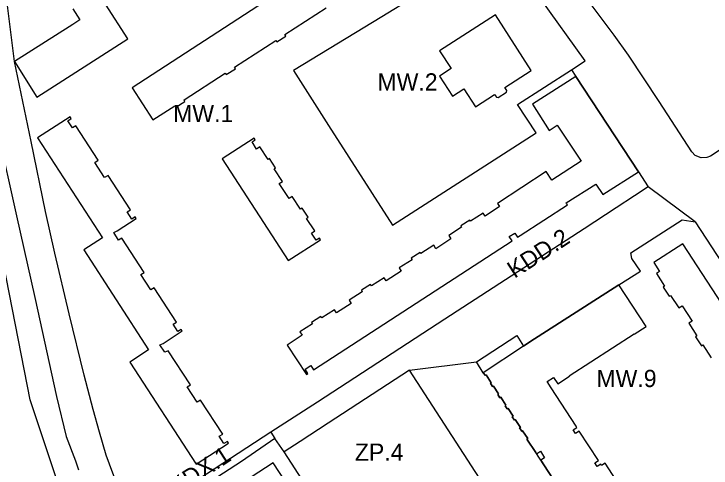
# Model space of a CAD drawing. Extents: x 7424052 to 7425705, y 5546602 to 5547569.
# Drawn here: x 7424769.6 to 7424972, y 5547200.9 to 5547332.7 of the extents above; entities that cross this region are included whole.
import ezdxf

# ---------------------------------------------------------------- set-up
doc = ezdxf.new("R2010")
doc.units = 0
for name, color, linetype in [('linie rozgraniczające', 7, 'Continuous'), ('nieprzekraczalne linie zabudowy', 7, 'Continuous'), ('obowiazujace linie zabudowy', 7, 'Continuous'), ('przeznaczenia terenów', 7, 'Continuous')]:
    doc.layers.add(name, color=color, linetype=linetype)

msp = doc.modelspace()

# ---------------------------------------------------------------- linework, layer by layer
at = {"layer": 'linie rozgraniczające'}
for p, q in [((7424910.29, 5547352.59), (7424876.38, 5547331.94)), ((7424943.81, 5547326.62), (7424931.1, 5547343.77)), ((7424769.83, 5547318.95), (7424767.07, 5547340.61)), ((7424935.47, 5547319.1), (7424922.33, 5547337.45)), ((7424876.38, 5547331.94), (7424850.76, 5547316.34)), ((7424948.03, 5547320.79), (7424943.81, 5547326.62)), ((7424956.87, 5547307.29), (7424948.03, 5547320.79)), ((7424774.64, 5547295.74), (7424769.83, 5547318.95)), ((7424931.41, 5547316.49), (7424935.47, 5547319.1)), ((7424850.76, 5547316.34), (7424860.98, 5547300.34)), ((7424915.81, 5547306.47), (7424931.41, 5547316.49)), ((7424931.41, 5547316.49), (7424932.69, 5547314.55)), ((7424932.69, 5547314.55), (7424950.88, 5547286.89)), ((7424966.38, 5547292.73), (7424956.87, 5547307.29)), ((7424921.18, 5547298.19), (7424915.81, 5547306.47)), ((7424764.44, 5547300.62), (7424770.4, 5547274.14)), ((7424988.18, 5547302.22), (7424971.75, 5547291.5)), ((7424860.98, 5547300.34), (7424879.48, 5547271.4)), ((7424879.48, 5547271.4), (7424921.18, 5547298.19)), ((7424778.79, 5547275.39), (7424774.64, 5547295.74)), ((7424967.37, 5547291.63), (7424966.38, 5547292.73)), ((7424969.1, 5547290.96), (7424967.37, 5547291.63)), ((7424970.72, 5547291.07), (7424969.1, 5547290.96)), ((7424971.75, 5547291.5), (7424970.72, 5547291.07)), ((7424950.88, 5547286.89), (7424953.73, 5547282.55)), ((7424953.73, 5547282.55), (7424949.7, 5547279.92)), ((7424967.35, 5547272.4), (7424953.73, 5547282.55)), ((7424949.7, 5547279.92), (7424944.41, 5547276.45)), ((7424944.41, 5547276.45), (7424935.15, 5547270.42)), ((7424770.4, 5547274.14), (7424775.71, 5547250.48)), ((7424781.47, 5547263.28), (7424778.79, 5547275.39)), ((7424948.65, 5547263.37), (7424963.59, 5547272.95)), ((7424963.59, 5547272.95), (7424967.35, 5547272.4)), ((7424967.35, 5547272.4), (7425007.07, 5547211.22)), ((7424935.15, 5547270.42), (7424894.68, 5547244.14)), ((7424785.68, 5547245.66), (7424781.47, 5547263.28)), ((7424948.95, 5547261.77), (7424948.65, 5547263.37)), ((7424951.45, 5547258.07), (7424948.95, 5547261.77)), ((7424945.18, 5547254.14), (7424951.45, 5547258.07)), ((7424919.41, 5547237.58), (7424945.18, 5547254.14)), ((7424775.71, 5547250.48), (7424781.99, 5547221.75)), ((7424789.98, 5547227.95), (7424785.68, 5547245.66)), ((7424894.68, 5547244.14), (7424857.73, 5547220.11)), ((7424903.86, 5547231.82), (7424915.61, 5547239.38)), ((7424915.61, 5547239.38), (7424917.57, 5547236.35)), ((7424917.57, 5547236.35), (7424919.41, 5547237.58)), ((7424884.42, 5547229.37), (7424903.86, 5547231.82)), ((7424905.84, 5547228.59), (7424903.86, 5547231.82)), ((7424792.66, 5547217.92), (7424789.98, 5547227.95)), ((7424884.42, 5547229.37), (7424860.86, 5547213.93)), ((7424905.84, 5547196.33), (7424884.42, 5547229.37)), ((7424906.46, 5547227.84), (7424905.84, 5547228.59)), ((7424906.71, 5547228), (7424906.46, 5547227.84)), ((7424908.17, 5547225.7), (7424906.71, 5547228)), ((7424907.91, 5547225.56), (7424908.17, 5547225.7)), ((7424908.56, 5547224.59), (7424907.91, 5547225.56)), ((7424908.81, 5547224.75), (7424908.56, 5547224.59)), ((7424910.29, 5547222.46), (7424908.81, 5547224.75)), ((7424781.99, 5547221.75), (7424784.83, 5547210.14)), ((7424910.05, 5547222.29), (7424910.29, 5547222.46)), ((7424910.67, 5547221.34), (7424910.05, 5547222.29)), ((7424857.73, 5547220.11), (7424844.22, 5547211.34)), ((7424910.93, 5547221.5), (7424910.67, 5547221.34)), ((7424912.41, 5547219.21), (7424910.93, 5547221.5)), ((7424794.43, 5547211.37), (7424792.66, 5547217.92)), ((7424912.17, 5547219.05), (7424912.41, 5547219.21)), ((7424912.79, 5547218.12), (7424912.17, 5547219.05)), ((7424913.04, 5547218.27), (7424912.79, 5547218.12)), ((7424914.52, 5547215.98), (7424913.04, 5547218.27)), ((7424914.28, 5547215.83), (7424914.52, 5547215.98)), ((7424914.91, 5547214.88), (7424914.28, 5547215.83)), ((7424860.86, 5547213.93), (7424852.68, 5547208.65)), ((7424915.15, 5547215.04), (7424914.91, 5547214.88)), ((7424916.64, 5547212.74), (7424915.15, 5547215.04)), ((7424916.39, 5547212.57), (7424916.64, 5547212.74)), ((7424917.03, 5547211.63), (7424916.39, 5547212.57)), ((7424917.23, 5547211.76), (7424917.03, 5547211.63)), ((7424918.74, 5547209.48), (7424917.23, 5547211.76)), ((7424784.83, 5547210.14), (7424787.48, 5547203.06)), ((7424796.45, 5547204.69), (7424794.43, 5547211.37)), ((7424844.22, 5547211.34), (7424803.72, 5547185.05)), ((7424845.37, 5547209.56), (7424835.69, 5547202.88)), ((7424844.22, 5547211.34), (7424845.37, 5547209.56)), ((7424848.08, 5547205.67), (7424845.37, 5547209.56)), ((7424918.51, 5547209.35), (7424918.74, 5547209.48)), ((7424852.68, 5547208.65), (7424848.08, 5547205.67)), ((7424921.08, 5547205.48), (7424918.51, 5547209.35)), ((7424869.3, 5547172.76), (7424848.08, 5547205.67)), ((7424928.48, 5547194.19), (7424921.08, 5547205.48)), ((7424803.72, 5547185.05), (7424796.45, 5547204.69)), ((7424787.48, 5547203.06), (7424788.42, 5547200.44)), ((7424835.69, 5547202.88), (7424804.56, 5547182.77))]:
    msp.add_line(p, q, dxfattribs=at)
at = {"layer": 'nieprzekraczalne linie zabudowy'}
for p, q in [((7424774.34, 5547220.72), (7424753.24, 5547328.2)), ((7424783.94, 5547191.96), (7424774.34, 5547220.72))]:
    msp.add_line(p, q, dxfattribs=at)
at = {"layer": 'obowiazujace linie zabudowy'}
for p, q in [((7424863.83, 5547350.2), (7424803.91, 5547311.34)), ((7424802.68, 5547325.47), (7424796.23, 5547335.59)), ((7424786.74, 5547334.23), (7424788.81, 5547331)), ((7424848.3, 5547326.8), (7424860.23, 5547334.52)), ((7424788.81, 5547331), (7424786.73, 5547329.68)), ((7424786.73, 5547329.68), (7424769.83, 5547318.95)), ((7424848.57, 5547326.33), (7424848.3, 5547326.8)), ((7424776.3, 5547308.56), (7424802.68, 5547325.47)), ((7424833.61, 5547317.29), (7424845.61, 5547325.06)), ((7424845.61, 5547325.06), (7424845.91, 5547324.6)), ((7424845.91, 5547324.6), (7424848.57, 5547326.33)), ((7424769.83, 5547318.95), (7424776.3, 5547308.56)), ((7424831.28, 5547315.13), (7424833.92, 5547316.81)), ((7424833.92, 5547316.81), (7424833.61, 5547317.29)), ((7424819, 5547307.82), (7424830.97, 5547315.57)), ((7424830.97, 5547315.57), (7424831.28, 5547315.13)), ((7424932.69, 5547314.55), (7424920.11, 5547306.55)), ((7424950.88, 5547286.89), (7424932.69, 5547314.55)), ((7424803.91, 5547311.34), (7424809.97, 5547301.97)), ((7424816.64, 5547305.64), (7424819.27, 5547307.36)), ((7424819.27, 5547307.36), (7424819, 5547307.82)), ((7424920.11, 5547306.55), (7424924.99, 5547298.94)), ((7424809.97, 5547301.97), (7424816.35, 5547306.1)), ((7424816.35, 5547306.1), (7424816.64, 5547305.64)), ((7424785.92, 5547302.86), (7424776.5, 5547296.79)), ((7424786.24, 5547302.37), (7424785.92, 5547302.86)), ((7424785.3, 5547301.75), (7424786.24, 5547302.37)), ((7424786.64, 5547299.64), (7424785.3, 5547301.75)), ((7424924.99, 5547298.94), (7424927.34, 5547300.5)), ((7424927.34, 5547300.5), (7424934.23, 5547290.01)), ((7424787.62, 5547300.24), (7424786.64, 5547299.64)), ((7424794.1, 5547290.28), (7424787.62, 5547300.24)), ((7424776.5, 5547296.79), (7424795.33, 5547267.77)), ((7424793.14, 5547289.67), (7424794.1, 5547290.28)), ((7424795.97, 5547285.23), (7424793.14, 5547289.67)), ((7424934.23, 5547290.01), (7424925.72, 5547284.46)), ((7424924.1, 5547286.97), (7424909.99, 5547277.75)), ((7424925.72, 5547284.46), (7424924.1, 5547286.97)), ((7424940.56, 5547280.32), (7424950.88, 5547286.89)), ((7424796.96, 5547285.87), (7424795.97, 5547285.23)), ((7424803.44, 5547275.92), (7424796.96, 5547285.87)), ((7424929.95, 5547277.89), (7424938.53, 5547283.36)), ((7424938.53, 5547283.36), (7424940.56, 5547280.32)), ((7424910.59, 5547276.85), (7424906.41, 5547274.05)), ((7424909.99, 5547277.75), (7424910.59, 5547276.85)), ((7424916.54, 5547268.41), (7424930.33, 5547277.3)), ((7424930.03, 5547277.77), (7424929.95, 5547277.89)), ((7424930.33, 5547277.3), (7424930.03, 5547277.77)), ((7424802.47, 5547275.27), (7424803.44, 5547275.92)), ((7424803.81, 5547273.19), (7424802.47, 5547275.27)), ((7424905.84, 5547274.9), (7424902.16, 5547272.56)), ((7424906.41, 5547274.05), (7424905.84, 5547274.9)), ((7424799.56, 5547269.76), (7424805.11, 5547273.34)), ((7424804.8, 5547273.82), (7424803.81, 5547273.19)), ((7424805.11, 5547273.34), (7424804.8, 5547273.82)), ((7424901.91, 5547272.91), (7424899.3, 5547271.21)), ((7424902.16, 5547272.56), (7424901.91, 5547272.91)), ((7424899.51, 5547270.83), (7424895.83, 5547268.46)), ((7424899.3, 5547271.21), (7424899.51, 5547270.83)), ((7424798.6, 5547269.31), (7424799.56, 5547269.76)), ((7424799.99, 5547267.08), (7424798.6, 5547269.31)), ((7424895.83, 5547268.46), (7424896.48, 5547267.47)), ((7424913.4, 5547268.17), (7424915.04, 5547269.16)), ((7424914.22, 5547266.91), (7424913.4, 5547268.17)), ((7424915.04, 5547269.16), (7424915.83, 5547267.95)), ((7424915.83, 5547267.95), (7424916.54, 5547268.41)), ((7424795.33, 5547267.77), (7424789.88, 5547264.25)), ((7424800.92, 5547267.67), (7424799.99, 5547267.08)), ((7424807.44, 5547257.69), (7424800.92, 5547267.67)), ((7424856.62, 5547229.47), (7424914.22, 5547266.91)), ((7424896.48, 5547267.47), (7424892.12, 5547264.58)), ((7424789.88, 5547264.25), (7424808.73, 5547235.21)), ((7424891.46, 5547265.63), (7424887.76, 5547263.24)), ((7424892.12, 5547264.58), (7424891.46, 5547265.63)), ((7424887.55, 5547263.54), (7424884.93, 5547261.85)), ((7424887.76, 5547263.24), (7424887.55, 5547263.54)), ((7424885.17, 5547261.41), (7424881.47, 5547259.02)), ((7424884.93, 5547261.85), (7424885.17, 5547261.41)), ((7424882.06, 5547258.06), (7424877.66, 5547255.29)), ((7424881.47, 5547259.02), (7424882.06, 5547258.06)), ((7424806.51, 5547257.1), (7424807.44, 5547257.69)), ((7424809.36, 5547252.7), (7424806.51, 5547257.1)), ((7424877.1, 5547256.19), (7424873.45, 5547253.83)), ((7424877.66, 5547255.29), (7424877.1, 5547256.19)), ((7424873.17, 5547254.25), (7424870.49, 5547252.55)), ((7424873.45, 5547253.83), (7424873.17, 5547254.25)), ((7424945.18, 5547254.14), (7424919.41, 5547237.58)), ((7424953.09, 5547242.06), (7424945.18, 5547254.14)), ((7424810.3, 5547253.29), (7424809.36, 5547252.7)), ((7424816.82, 5547243.3), (7424810.3, 5547253.29)), ((7424870.71, 5547252.12), (7424866.92, 5547249.67)), ((7424870.49, 5547252.55), (7424870.71, 5547252.12)), ((7424867.48, 5547248.72), (7424863.21, 5547245.96)), ((7424866.92, 5547249.67), (7424867.48, 5547248.72)), ((7424862.63, 5547246.9), (7424859, 5547244.55)), ((7424863.21, 5547245.96), (7424862.63, 5547246.9)), ((7424858.71, 5547244.95), (7424856, 5547243.21)), ((7424859, 5547244.55), (7424858.71, 5547244.95)), ((7424815.87, 5547242.66), (7424816.82, 5547243.3)), ((7424817.21, 5547240.57), (7424815.87, 5547242.66)), ((7424856.33, 5547242.78), (7424852.62, 5547240.44)), ((7424856, 5547243.21), (7424856.33, 5547242.78)), ((7424949.69, 5547239.84), (7424953.09, 5547242.06)), ((7424812.98, 5547237.12), (7424818.49, 5547240.73)), ((7424818.19, 5547241.2), (7424817.21, 5547240.57)), ((7424818.49, 5547240.73), (7424818.19, 5547241.2)), ((7424852.62, 5547240.44), (7424853.31, 5547239.49)), ((7424930.78, 5547227.74), (7424949.61, 5547239.94)), ((7424949.61, 5547239.94), (7424949.69, 5547239.84)), ((7424853.31, 5547239.49), (7424848.96, 5547236.63)), ((7424812, 5547236.68), (7424812.98, 5547237.12)), ((7424813.39, 5547234.53), (7424812, 5547236.68)), ((7424848.96, 5547236.63), (7424854.54, 5547228.12)), ((7424917.57, 5547236.35), (7424905.84, 5547228.59)), ((7424919.41, 5547237.58), (7424917.57, 5547236.35)), ((7424808.73, 5547235.21), (7424803.29, 5547231.68)), ((7424814.36, 5547235.01), (7424813.39, 5547234.53)), ((7424820.87, 5547225.05), (7424814.36, 5547235.01)), ((7424803.29, 5547231.68), (7424822.49, 5547202.06)), ((7424854.17, 5547229.63), (7424855.8, 5547230.7)), ((7424854.97, 5547228.4), (7424854.17, 5547229.63)), ((7424855.8, 5547230.7), (7424856.62, 5547229.47)), ((7424854.54, 5547228.12), (7424854.97, 5547228.4)), ((7424905.84, 5547228.59), (7424906.46, 5547227.84)), ((7424906.46, 5547227.84), (7424906.71, 5547228)), ((7424906.71, 5547228), (7424908.17, 5547225.7)), ((7424927.47, 5547225.41), (7424930.86, 5547227.61)), ((7424930.86, 5547227.61), (7424930.78, 5547227.74)), ((7424908.17, 5547225.7), (7424907.91, 5547225.56)), ((7424924.35, 5547226.03), (7424926.24, 5547227.26)), ((7424925.55, 5547224.19), (7424924.35, 5547226.03)), ((7424926.24, 5547227.26), (7424927.47, 5547225.41)), ((7424819.95, 5547224.47), (7424820.87, 5547225.05)), ((7424822.85, 5547220.1), (7424819.95, 5547224.47)), ((7424907.91, 5547225.56), (7424908.56, 5547224.59)), ((7424908.56, 5547224.59), (7424908.81, 5547224.75)), ((7424908.81, 5547224.75), (7424910.29, 5547222.46)), ((7424932.8, 5547213.08), (7424925.55, 5547224.19)), ((7424910.29, 5547222.46), (7424910.05, 5547222.29)), ((7424910.05, 5547222.29), (7424910.67, 5547221.34)), ((7424823.74, 5547220.67), (7424822.85, 5547220.1)), ((7424830.23, 5547210.75), (7424823.74, 5547220.67)), ((7424910.67, 5547221.34), (7424910.93, 5547221.5)), ((7424910.93, 5547221.5), (7424912.41, 5547219.21)), ((7424912.41, 5547219.21), (7424912.17, 5547219.05)), ((7424912.17, 5547219.05), (7424912.79, 5547218.12)), ((7424912.79, 5547218.12), (7424913.04, 5547218.27)), ((7424913.04, 5547218.27), (7424914.52, 5547215.98)), ((7424914.52, 5547215.98), (7424914.28, 5547215.83)), ((7424914.28, 5547215.83), (7424914.91, 5547214.88)), ((7424914.91, 5547214.88), (7424915.15, 5547215.04)), ((7424915.15, 5547215.04), (7424916.64, 5547212.74)), ((7424916.64, 5547212.74), (7424916.39, 5547212.57)), ((7424916.39, 5547212.57), (7424917.03, 5547211.63)), ((7424917.03, 5547211.63), (7424917.23, 5547211.76)), ((7424917.23, 5547211.76), (7424918.74, 5547209.48)), ((7424931.95, 5547212), (7424933.04, 5547212.71)), ((7424932.63, 5547210.97), (7424931.95, 5547212)), ((7424933.72, 5547211.66), (7424932.63, 5547210.97)), ((7424933.04, 5547212.71), (7424932.8, 5547213.08)), ((7424939.28, 5547203.15), (7424933.72, 5547211.66)), ((7424829.22, 5547210.2), (7424830.23, 5547210.75)), ((7424830.58, 5547208.08), (7424829.22, 5547210.2)), ((7424918.74, 5547209.48), (7424918.51, 5547209.35)), ((7424822.49, 5547202.06), (7424831.89, 5547208.21)), ((7424831.61, 5547208.64), (7424830.58, 5547208.08)), ((7424831.89, 5547208.21), (7424831.61, 5547208.64)), ((7424918.51, 5547209.35), (7424921.08, 5547205.48)), ((7424921.08, 5547205.48), (7424921.33, 5547205.11)), ((7424921.33, 5547205.11), (7424922.42, 5547205.8)), ((7424922.42, 5547205.8), (7424923.62, 5547203.94)), ((7424923.62, 5547203.94), (7424922.55, 5547203.23)), ((7424922.55, 5547203.23), (7424927.05, 5547196.38)), ((7424938.23, 5547202.47), (7424939.28, 5547203.15)), ((7424938.9, 5547201.44), (7424938.23, 5547202.47)), ((7424939.96, 5547202.11), (7424938.9, 5547201.44)), ((7424940.21, 5547201.73), (7424939.96, 5547202.11)), ((7424941.21, 5547202.37), (7424940.21, 5547201.73)), ((7424948.65, 5547191.04), (7424941.21, 5547202.37))]:
    msp.add_line(p, q, dxfattribs=at)
for points in [[(7424893.19, 5547322.03), (7424896.5, 5547316.86), (7424893.16, 5547314.67), (7424896.92, 5547308.89), (7424900.25, 5547311.01), (7424903.58, 5547305.82), (7424909.13, 5547309.4), (7424909.69, 5547308.59), (7424910.15, 5547308.51), (7424912.57, 5547310.08), (7424912.65, 5547310.52), (7424912.11, 5547311.37), (7424919.79, 5547316.33), (7424909.41, 5547332.47), (7424893.19, 5547322.03)], [(7424830.07, 5547290.69), (7424849.23, 5547261.19), (7424858.62, 5547267.16), (7424858.31, 5547267.64), (7424857.33, 5547267.1), (7424856.02, 5547269.12), (7424856.93, 5547269.75), (7424854.57, 5547273.38), (7424855.02, 5547273.77), (7424853.32, 5547276.34), (7424852.83, 5547276.05), (7424850.43, 5547279.74), (7424849.51, 5547279.14), (7424846.61, 5547283.55), (7424847.55, 5547284.15), (7424845.17, 5547287.8), (7424845.56, 5547288.12), (7424843.85, 5547290.76), (7424843.43, 5547290.48), (7424841.03, 5547294.16), (7424840.06, 5547293.54), (7424838.76, 5547295.58), (7424839.68, 5547296.25), (7424839.36, 5547296.73), (7424830.07, 5547290.69)], [(7425001.78, 5547207.7), (7424963.81, 5547266.06), (7424955.38, 5547260.59), (7424957.02, 5547257.97)], [(7424957.02, 5547257.97), (7424956.1, 5547257.38), (7424958.48, 5547253.72), (7424958.04, 5547253.41), (7424959.85, 5547250.81), (7424960.22, 5547251.05), (7424962.6, 5547247.41), (7424963.6, 5547248.06), (7424966.46, 5547243.61), (7424965.48, 5547242.98), (7424967.86, 5547239.33), (7424967.46, 5547239.06), (7424969.18, 5547236.4), (7424969.6, 5547236.67), (7424972.01, 5547232.96)], [(7424850.22, 5547194.37), (7424844.87, 5547202.45), (7424838.45, 5547198.28)]]:
    msp.add_lwpolyline(points, dxfattribs=at)

# ---------------------------------------------------------------- texts
at = {"layer": 'przeznaczenia terenów'}
for s, p in [('MW.2', (7424875.14, 5547310.51)), ('MW.1', (7424815.84, 5547301.34)), ('MW.9', (7424938.69, 5547224.45)), ('ZP.4', (7424868.58, 5547203.06))]:
    msp.add_text(s, height=5, dxfattribs=at).set_placement(p)
for s, p in [('KDD.2', (7424914.91, 5547255.84)), ('KDX.1', (7424816.87, 5547192.83))]:
    msp.add_text(s, height=5, rotation=33, dxfattribs=at).set_placement(p)

doc.saveas('drawing.dxf')
